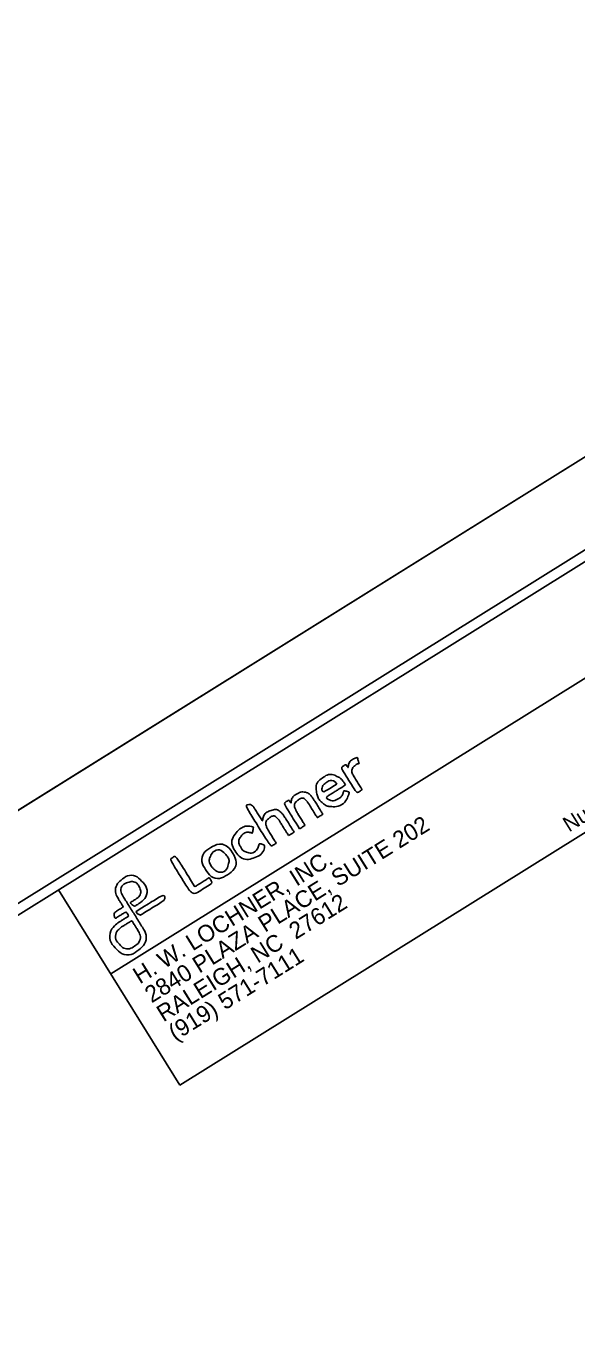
# Model space of a CAD drawing. Extents: x 2047559 to 2049567, y 759970 to 761789.
# Drawn here: x 2048671.6 to 2048811.1, y 761456 to 761789.3 of the extents above; entities that cross this region are included whole.
import ezdxf

# ---------------------------------------------------------------- set-up
doc = ezdxf.new("R2010")
doc.units = 0
for name, color, linetype in [('Default', 7, 'Continuous'), ('Old_Level_4', 7, 'Continuous'), ('Sheet Cutting Line CELL', 7, 'Continuous'), ('Sheet Plan CELL', 7, 'Continuous'), ('Sheet Plot Border Inside CELL', 7, 'Continuous'), ('Sheet Plot Border Outside CELL', 7, 'Continuous')]:
    doc.layers.add(name, color=color, linetype=linetype)

msp = doc.modelspace()

# ---------------------------------------------------------------- linework, layer by layer
at = {"layer": 'Default'}
msp.add_line((2048693.02, 761549.62), (2048828.87, 761634.21), dxfattribs=at)
for points in [[(2048755.5, 761604.26), (2048755.48, 761604.28), (2048755.47, 761604.3), (2048755.45, 761604.33), (2048755.42, 761604.31), (2048755.39, 761604.29), (2048755.36, 761604.28), (2048754.17, 761603.89), (2048753.37, 761603.15), (2048753.16, 761601.88), (2048753.16, 761601.85), (2048753.14, 761601.84), (2048753.1, 761601.79), (2048752.92, 761602.07), (2048752.76, 761602.33), (2048752.6, 761602.59), (2048752.15, 761602.31), (2048751.73, 761602.05), (2048751.31, 761601.79), (2048752.65, 761599.62), (2048754, 761597.47), (2048755.34, 761595.31), (2048755.81, 761595.6), (2048756.26, 761595.88), (2048756.73, 761596.18), (2048756.68, 761596.26), (2048756.64, 761596.33), (2048756.6, 761596.39), (2048755.91, 761597.5), (2048755.22, 761598.6), (2048754.53, 761599.71), (2048753.98, 761600.6), (2048754.14, 761601.62), (2048754.93, 761602.32), (2048755.22, 761602.57), (2048755.56, 761602.71), (2048755.95, 761602.79), (2048755.93, 761602.86), (2048755.91, 761602.93), (2048755.89, 761602.99), (2048755.76, 761603.41), (2048755.63, 761603.83), (2048755.5, 761604.26)], [(2048752.51, 761597.39), (2048752.36, 761597.63), (2048752.23, 761597.85), (2048752.09, 761598.06), (2048751.65, 761598.67), (2048751.12, 761599.18), (2048750.44, 761599.51), (2048749.1, 761600.16), (2048747.83, 761600.01), (2048746.64, 761599.14), (2048745.37, 761598.2), (2048744.9, 761596.92), (2048745.2, 761595.39), (2048745.4, 761594.33), (2048745.96, 761593.45), (2048746.78, 761592.76), (2048747.37, 761592.25), (2048748.07, 761591.97), (2048748.84, 761591.91), (2048750.62, 761591.78), (2048752.53, 761592.99), (2048753.21, 761594.69), (2048753.33, 761594.98), (2048753.4, 761595.28), (2048753.49, 761595.59), (2048753, 761595.72), (2048752.55, 761595.84), (2048752.1, 761595.96), (2048752.07, 761595.88), (2048752.05, 761595.81), (2048752.03, 761595.74), (2048751.77, 761594.87), (2048751.25, 761594.2), (2048750.44, 761593.76), (2048749.78, 761593.41), (2048749.1, 761593.3), (2048748.39, 761593.61), (2048748.05, 761593.76), (2048747.78, 761593.98), (2048747.55, 761594.3), (2048748.39, 761594.83), (2048749.21, 761595.33), (2048750.03, 761595.84), (2048750.85, 761596.36), (2048751.67, 761596.87), (2048752.51, 761597.39)], [(2048750.32, 761597.62), (2048749.17, 761596.9), (2048748.02, 761596.18), (2048746.87, 761595.47), (2048746.39, 761596.06), (2048746.72, 761597.34), (2048747.49, 761597.91), (2048748.51, 761598.65), (2048749.72, 761598.53), (2048750.32, 761597.62)], [(2048740.86, 761586.3), (2048741.33, 761586.59), (2048741.78, 761586.88), (2048742.25, 761587.17), (2048742.2, 761587.25), (2048742.16, 761587.32), (2048742.12, 761587.39), (2048741.48, 761588.42), (2048740.84, 761589.44), (2048740.21, 761590.46), (2048740.07, 761590.69), (2048739.95, 761590.92), (2048739.85, 761591.17), (2048739.49, 761592.08), (2048739.7, 761592.95), (2048740.42, 761593.53), (2048741.11, 761594.07), (2048741.9, 761594.15), (2048742.58, 761593.44), (2048742.71, 761593.3), (2048742.84, 761593.14), (2048742.95, 761592.97), (2048743.71, 761591.75), (2048744.47, 761590.53), (2048745.23, 761589.3), (2048745.28, 761589.24), (2048745.32, 761589.17), (2048745.36, 761589.1), (2048745.84, 761589.41), (2048746.3, 761589.69), (2048746.77, 761589.98), (2048746.72, 761590.06), (2048746.68, 761590.12), (2048746.64, 761590.18), (2048745.92, 761591.34), (2048745.21, 761592.49), (2048744.49, 761593.64), (2048744.32, 761593.9), (2048744.16, 761594.15), (2048743.97, 761594.39), (2048743.46, 761595.04), (2048742.82, 761595.49), (2048741.98, 761595.59), (2048741.39, 761595.66), (2048740.84, 761595.5), (2048740.33, 761595.21), (2048739.44, 761594.72), (2048738.86, 761594), (2048738.73, 761592.97), (2048738.73, 761592.92), (2048738.71, 761592.88), (2048738.7, 761592.78), (2048738.51, 761593.08), (2048738.35, 761593.34), (2048738.18, 761593.61), (2048737.72, 761593.32), (2048737.28, 761593.05), (2048736.83, 761592.77), (2048738.17, 761590.61), (2048739.51, 761588.46), (2048740.86, 761586.3)], [(2048738.08, 761584.56), (2048738.56, 761584.86), (2048739.01, 761585.15), (2048739.48, 761585.44), (2048739.45, 761585.49), (2048739.43, 761585.53), (2048739.41, 761585.57), (2048738.63, 761586.82), (2048737.85, 761588.08), (2048737.06, 761589.32), (2048736.9, 761589.59), (2048736.71, 761589.84), (2048736.5, 761590.07), (2048735.72, 761590.9), (2048734.79, 761591.31), (2048733.66, 761590.93), (2048732.48, 761590.55), (2048731.7, 761589.76), (2048731.5, 761588.49), (2048731.5, 761588.43), (2048731.48, 761588.38), (2048731.46, 761588.26), (2048731.38, 761588.38), (2048731.35, 761588.44), (2048731.31, 761588.5), (2048730.64, 761589.57), (2048729.98, 761590.64), (2048729.3, 761591.71), (2048729.21, 761591.85), (2048729.09, 761591.99), (2048728.96, 761592.09), (2048728.46, 761592.48), (2048727.58, 761592.46), (2048727.17, 761592.06), (2048729.3, 761588.63), (2048731.44, 761585.2), (2048733.58, 761581.77), (2048734.04, 761582.06), (2048734.5, 761582.34), (2048734.96, 761582.63), (2048734.91, 761582.71), (2048734.87, 761582.78), (2048734.82, 761582.85), (2048734.2, 761583.85), (2048733.57, 761584.85), (2048732.96, 761585.86), (2048732.8, 761586.11), (2048732.67, 761586.38), (2048732.56, 761586.65), (2048732.21, 761587.56), (2048732.41, 761588.41), (2048733.14, 761588.99), (2048733.85, 761589.56), (2048734.65, 761589.6), (2048735.31, 761588.88), (2048735.45, 761588.73), (2048735.59, 761588.56), (2048735.7, 761588.38), (2048736.18, 761587.61), (2048736.66, 761586.85), (2048737.13, 761586.08), (2048737.44, 761585.58), (2048737.76, 761585.08), (2048738.08, 761584.56)], [(2048729.18, 761586.69), (2048727.8, 761587.25), (2048725.92, 761586.65), (2048724.79, 761585.26), (2048723.66, 761583.85), (2048723.64, 761581.96), (2048724.76, 761580.36), (2048725.74, 761578.95), (2048727.51, 761578.35), (2048729.13, 761578.89), (2048730.8, 761579.44), (2048731.94, 761580.76), (2048732.05, 761582.21), (2048731.57, 761582.33), (2048731.09, 761582.46), (2048730.65, 761582.57), (2048730.6, 761582.4), (2048730.54, 761582.26), (2048730.5, 761582.1), (2048730.16, 761580.76), (2048728.64, 761579.94), (2048727.35, 761580.41), (2048726.66, 761580.65), (2048726.21, 761581.15), (2048725.88, 761581.77), (2048725.41, 761582.63), (2048725.49, 761583.72), (2048726.09, 761584.45), (2048726.71, 761585.22), (2048727.75, 761585.53), (2048728.71, 761585.23), (2048728.76, 761585.22), (2048728.81, 761585.19), (2048728.91, 761585.16), (2048729, 761585.69), (2048729.09, 761586.18), (2048729.18, 761586.69)], [(2048723.91, 761580.24), (2048722.69, 761582.19), (2048720.29, 761582.75), (2048718.35, 761581.54), (2048716.4, 761580.33), (2048715.84, 761577.92), (2048717.05, 761575.98), (2048718.26, 761574.03), (2048720.66, 761573.45), (2048722.59, 761574.65), (2048724.57, 761575.88), (2048725.13, 761578.27), (2048723.91, 761580.24)], [(2048718.54, 761576.77), (2048718.04, 761577.61), (2048717.87, 761578.4), (2048718.23, 761579.24), (2048718.78, 761580.52), (2048720.66, 761581.29), (2048722.04, 761579.9), (2048722.75, 761579.18), (2048723.1, 761578.3), (2048722.84, 761577.28), (2048722.4, 761575.56), (2048720.24, 761575.01), (2048718.96, 761576.28), (2048718.78, 761576.45), (2048718.63, 761576.66), (2048718.54, 761576.77)], [(2048714.34, 761571.65), (2048712.7, 761574.27), (2048711.08, 761576.88), (2048709.45, 761579.49), (2048708.95, 761579.18), (2048708.48, 761578.88), (2048707.99, 761578.58), (2048709.9, 761575.51), (2048711.8, 761572.45), (2048713.71, 761569.39), (2048715.42, 761570.45), (2048717.12, 761571.51), (2048718.84, 761572.58), (2048718.59, 761572.97), (2048718.35, 761573.35), (2048718.12, 761573.73), (2048718.03, 761573.89), (2048717.96, 761573.91), (2048717.8, 761573.81), (2048716.73, 761573.13), (2048715.65, 761572.46), (2048714.57, 761571.79), (2048714.5, 761571.75), (2048714.43, 761571.71), (2048714.34, 761571.65)], [(2048697.62, 761564.23), (2048697.54, 761564.18), (2048697.47, 761564.14), (2048697.41, 761564.1), (2048696.67, 761563.64), (2048695.93, 761563.19), (2048695.2, 761562.72), (2048694.95, 761562.56), (2048694.71, 761562.38), (2048694.49, 761562.18), (2048692.77, 761560.65), (2048692.62, 761557.85), (2048694.17, 761556.15), (2048695.77, 761554.41), (2048698.29, 761554.21), (2048700.15, 761555.68), (2048701.8, 761556.99), (2048702.24, 761559.46), (2048701.13, 761561.24), (2048699.47, 761563.91), (2048697.8, 761566.57), (2048696.14, 761569.25), (2048695.33, 761570.55), (2048695.95, 761572.26), (2048697.41, 761572.74), (2048698.5, 761573.1), (2048699.73, 761572.6), (2048700.24, 761571.59), (2048700.78, 761570.53), (2048700.46, 761569.24), (2048699.47, 761568.57), (2048699.05, 761568.28), (2048698.61, 761568.02), (2048698.17, 761567.74), (2048698.11, 761567.7), (2048698.05, 761567.65), (2048697.97, 761567.6), (2048698.26, 761567.21), (2048698.58, 761566.91), (2048699.01, 761566.74), (2048699.07, 761566.72), (2048699.15, 761566.73), (2048699.2, 761566.76), (2048699.63, 761567.03), (2048700.07, 761567.28), (2048700.47, 761567.59), (2048702.15, 761568.9), (2048702.43, 761571.46), (2048700.82, 761573.1), (2048699.39, 761574.57), (2048697.19, 761574.63), (2048695.62, 761573.27), (2048694.4, 761572.21), (2048694.02, 761570.27), (2048694.8, 761568.84), (2048695.19, 761568.13), (2048695.64, 761567.44), (2048696.07, 761566.75), (2048696.11, 761566.68), (2048696.15, 761566.61), (2048696.21, 761566.52), (2048696.12, 761566.47), (2048696.06, 761566.43), (2048695.99, 761566.39), (2048695.5, 761566.08), (2048695.01, 761565.78), (2048694.53, 761565.47), (2048694.02, 761565.15), (2048693.79, 761564.57), (2048693.97, 761563.99), (2048694.01, 761563.86), (2048694.08, 761563.74), (2048694.15, 761563.6), (2048695.1, 761564.19), (2048696.01, 761564.76), (2048696.93, 761565.33), (2048697.16, 761564.96), (2048697.38, 761564.61), (2048697.62, 761564.23)], [(2048699.39, 761565.32), (2048699.68, 761564.94), (2048700.01, 761564.65), (2048700.44, 761564.48), (2048700.51, 761564.46), (2048700.62, 761564.48), (2048700.69, 761564.52), (2048702.46, 761565.62), (2048704.24, 761566.72), (2048706.01, 761567.83), (2048706.65, 761568.23), (2048706.81, 761569.13), (2048706.36, 761569.66), (2048704.04, 761568.22), (2048701.73, 761566.78), (2048699.39, 761565.32)], [(2048698.35, 761563.05), (2048698.28, 761563.01), (2048698.24, 761562.98), (2048698.19, 761562.95), (2048697.41, 761562.47), (2048696.62, 761561.98), (2048695.84, 761561.49), (2048695.69, 761561.39), (2048695.55, 761561.28), (2048695.41, 761561.16), (2048694.25, 761560.12), (2048694.17, 761558.19), (2048695.22, 761557.06), (2048696.27, 761555.94), (2048697.81, 761555.77), (2048699.09, 761556.61), (2048700.29, 761557.41), (2048700.73, 761559.13), (2048700.02, 761560.37), (2048699.51, 761561.25), (2048698.96, 761562.09), (2048698.43, 761562.95), (2048698.41, 761562.98), (2048698.39, 761563.01), (2048698.35, 761563.05)], [(2048698.35, 761563.05), (2048698.39, 761563.01), (2048698.41, 761562.98), (2048698.43, 761562.95), (2048698.96, 761562.09), (2048699.51, 761561.25), (2048700.02, 761560.37), (2048700.73, 761559.13), (2048700.29, 761557.41), (2048699.09, 761556.61), (2048697.81, 761555.77), (2048696.27, 761555.94), (2048695.22, 761557.06), (2048694.17, 761558.19), (2048694.25, 761560.12), (2048695.41, 761561.16), (2048695.55, 761561.28), (2048695.69, 761561.39), (2048695.84, 761561.49), (2048696.62, 761561.98), (2048697.41, 761562.47), (2048698.19, 761562.95), (2048698.24, 761562.98), (2048698.28, 761563.01), (2048698.35, 761563.05)], [(2048698.35, 761563.05), (2048698.39, 761563.01), (2048698.41, 761562.98), (2048698.43, 761562.95), (2048698.96, 761562.09), (2048699.51, 761561.25), (2048700.02, 761560.37), (2048700.73, 761559.13), (2048700.29, 761557.41), (2048699.09, 761556.61), (2048697.81, 761555.77), (2048696.27, 761555.94), (2048695.22, 761557.06), (2048694.17, 761558.19), (2048694.25, 761560.12), (2048695.41, 761561.16), (2048695.55, 761561.28), (2048695.69, 761561.39), (2048695.84, 761561.49), (2048696.62, 761561.98), (2048697.41, 761562.47), (2048698.19, 761562.95), (2048698.24, 761562.98), (2048698.28, 761563.01), (2048698.35, 761563.05)]]:
    msp.add_open_spline(points, degree=3, dxfattribs=at)
at = {"layer": 'Old_Level_4'}
for q in [(2048846.4, 761606.07), (2048679.79, 761570.86)]:
    msp.add_line((2048710.56, 761521.46), q, dxfattribs=at)
at = {"layer": 'Sheet Cutting Line CELL'}
msp.add_line((2048987.97, 761789.33), (2047559, 760899.25), dxfattribs=at)
at = {"layer": 'Sheet Plan CELL'}
msp.add_lwpolyline([(2048985.43, 761761.24), (2047712.23, 760968.18), (2048267.37, 760076.94), (2049540.57, 760870)], close=True, dxfattribs=at)
at = {"layer": 'Sheet Plot Border Inside CELL'}
msp.add_lwpolyline([(2048138.4, 759993.66), (2049552.51, 760874.48), (2048994.72, 761769.97), (2047580.61, 760889.15)], close=True, dxfattribs=at)
at = {"layer": 'Sheet Plot Border Outside CELL'}
msp.add_lwpolyline([(2048137.94, 759969.81), (2049566.9, 760859.89), (2048987.97, 761789.33), (2047559, 760899.25)], close=True, dxfattribs=at)

# ---------------------------------------------------------------- texts
at = {"layer": 'Default'}
for s, height, p in [('Number F-0159', 3.865, (2048809.13, 761585.34)), ('2840 PLAZA PLACE, SUITE 202', 4.2515, (2048703.38, 761542.09)), ('H. W. LOCHNER, INC.', 4.2515, (2048700.38, 761546.9)), ('RALEIGH, NC  27612', 4.2515, (2048706.37, 761537.29)), ('(919) 571-7111', 4.2515, (2048709.36, 761532.48))]:
    msp.add_text(s, height=height, rotation=31.9169, dxfattribs=at).set_placement(p)

doc.saveas('drawing.dxf')
